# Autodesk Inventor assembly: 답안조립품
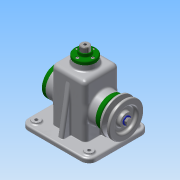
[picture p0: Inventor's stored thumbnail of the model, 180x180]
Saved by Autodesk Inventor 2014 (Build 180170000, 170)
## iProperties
Created: 2015-12
Part Number: 답안조립품
Document SubType Name: Assembly
Designer: Administrator
Author: Administrator
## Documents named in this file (19)
- D:\451225V1002\답안조립품.iam
- D:\451225V1002\1-본체.ipt
- D:\451225V1002\고정핀.ipt
- D:\451225V1002\뒤커버.ipt
- D:\451225V1002\링크.ipt
- D:\451225V1002\멈춤링 6 x 5.ipt
- D:\451225V1002\멈춤링 15 x 1.ipt
- D:\451225V1002\베어링 15 x 35 x 11.ipt
- D:\451225V1002\볼트 M3 x 8.ipt
- D:\451225V1002\볼트 M4 x 10.ipt
- D:\451225V1002\볼트 M6 x 12.ipt
- D:\451225V1002\상부부시.ipt
- D:\451225V1002\슬라이드바.ipt
- D:\451225V1002\앞커버.ipt
- D:\451225V1002\오일실 15 25 7.ipt
- D:\451225V1002\와셔.ipt
- D:\451225V1002\키 5 x 5 x 14.ipt
- D:\451225V1002\편심축.ipt
- D:\451225V1002\V-벨트풀리.ipt
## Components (12 placed, 6 different names)
1. 1-본체:1
2. 고정핀:1 — 플러쉬:2
3. ISO 4018 M6 x 12:1 — 각도:3
4. V-벨트풀리:1 — 각도:2
5. ISO 4762 M3 x 8:1
6. ISO 4762 M3 x 8:2
7. ISO 4762 M3 x 8:3
8. ISO 4762 M3 x 8:4
9. ISO 4762 M4 x 10:1
10. ISO 4762 M4 x 10:2
11. ISO 4762 M4 x 10:3
12. ISO 4762 M4 x 10:4
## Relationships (3: Angle 2, Flush 1)
- 각도:2 [Angle]: V-벨트풀리:1
- 각도:3 [Angle]: ISO 4018 M6 x 12:1
- 플러쉬:2 [Flush]: 고정핀:1
